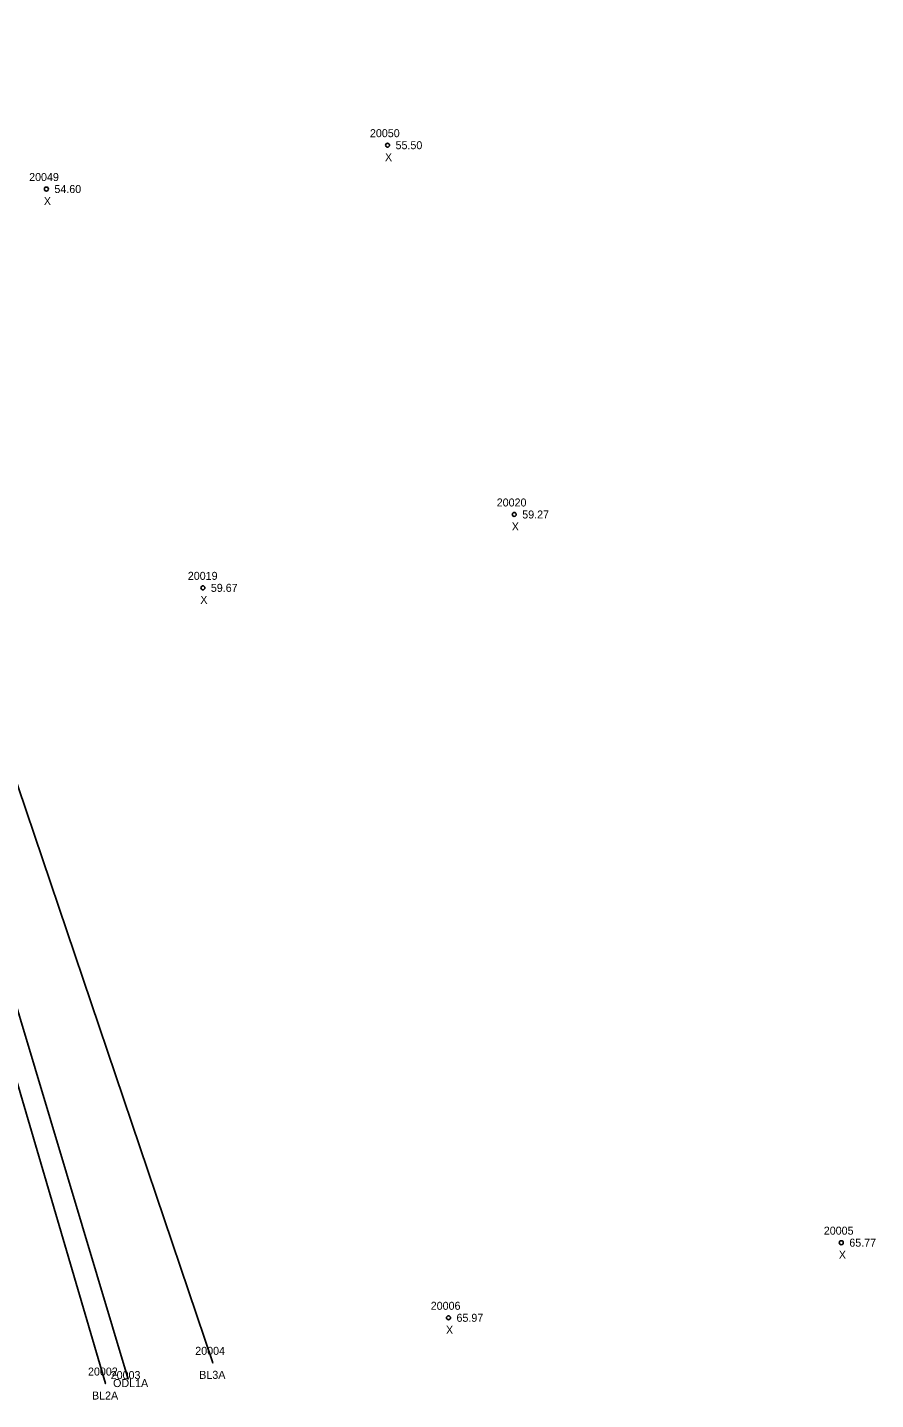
# Model space of a CAD drawing. Extents: x 2445178 to 2446260, y 791158 to 792318.
# Drawn here: x 2445873 to 2445979.1, y 791182.8 to 791354.3 of the extents above; entities that cross this region are included whole.
import ezdxf

# ---------------------------------------------------------------- set-up
doc = ezdxf.new("R2010")
doc.units = 0
for name, color, linetype in [('RD_DTM_BkLn1', 7, 'Continuous'), ('RD_EX_H2O', 7, 'Continuous'), ('RD_EX_H2O_txCode', 7, 'Continuous'), ('RD_Sketch8', 7, 'Continuous'), ('RD_SMD_Locator', 7, 'Continuous'), ('RD_SMD_Misc', 7, 'Continuous')]:
    doc.layers.add(name, color=color, linetype=linetype)

msp = doc.modelspace()

# ---------------------------------------------------------------- linework, layer by layer
at = {"layer": 'RD_DTM_BkLn1'}
for points in [[(2445882.78, 791184.78), (2445856.18, 791275.27), (2445839.04, 791329.43), (2445822.96, 791388.68), (2445805.7, 791444.65), (2445792.52, 791499.62), (2445777.56, 791559.78), (2445760.75, 791635.11), (2445757, 791668.89), (2445761.65, 791682.26), (2445806.3, 791698.85), (2445844.78, 791714.67)], [(2445896.2, 791187.37), (2445865.75, 791277.36), (2445863.45, 791286.42), (2445844.64, 791330.14), (2445831.75, 791389.47), (2445816.24, 791445.72), (2445804.21, 791499.93), (2445790.09, 791561.7), (2445779.57, 791613.54), (2445773.51, 791630.61), (2445764.7, 791668.39), (2445768.27, 791675.25), (2445808.12, 791695.24), (2445844.78, 791714.67)]]:
    msp.add_lwpolyline(points, dxfattribs=at)
at = {"layer": 'RD_EX_H2O'}
msp.add_lwpolyline([(2445885.63, 791185.34), (2445858.54, 791275.66), (2445841.27, 791329.71), (2445824.98, 791389.05), (2445808.2, 791445.07), (2445795.15, 791500.08), (2445780.4, 791559.92), (2445764.43, 791632.51), (2445759.72, 791668.56), (2445764.88, 791679.11), (2445806.8, 791696.09), (2445844.78, 791714.67)], dxfattribs=at)
at = {"layer": 'RD_SMD_Locator'}
for centre, radius in [((2445918.04, 791339.57), 0.25), ((2445875.39, 791334.09), 0.25), ((2445933.88, 791293.41), 0.25), ((2445894.95, 791284.24), 0.25), ((2445974.77, 791202.39), 0.25), ((2445925.66, 791193), 0.25), ((2445896.2, 791187.37), 0.001), ((2445882.78, 791184.78), 0.001), ((2445885.63, 791185.34), 0.001)]:
    msp.add_circle(centre, radius, dxfattribs=at)

# ---------------------------------------------------------------- texts
at = {"layer": 'RD_EX_H2O_txCode'}
for s, p in [('20003', (2445883.43, 791185.34)), ('ODL1A', (2445883.73, 791184.34))]:
    msp.add_text(s, height=1, dxfattribs=at).set_placement(p)
at = {"layer": 'RD_Sketch8'}
for s, p in [('20050', (2445915.84, 791340.57)), ('55.50', (2445919.04, 791339.07)), ('X', (2445917.72, 791337.57)), ('20049', (2445873.23, 791335.09)), ('54.60', (2445876.39, 791333.59)), ('X', (2445875.07, 791332.09)), ('20020', (2445931.69, 791294.41)), ('59.27', (2445934.88, 791292.91)), ('X', (2445933.57, 791291.41)), ('20019', (2445893.07, 791285.24)), ('59.67', (2445895.95, 791283.74)), ('X', (2445894.63, 791282.24)), ('20005', (2445972.58, 791203.39)), ('65.77', (2445975.77, 791201.89)), ('X', (2445974.46, 791200.39)), ('20006', (2445923.44, 791194)), ('65.97', (2445926.66, 791192.5)), ('X', (2445925.35, 791191))]:
    msp.add_text(s, height=1, dxfattribs=at).set_placement(p)
at = {"layer": 'RD_SMD_Misc'}
for s, p in [('20004', (2445894, 791188.37)), ('20002', (2445880.59, 791185.78)), ('BL3A', (2445894.5, 791185.37)), ('BL2A', (2445881.09, 791182.78))]:
    msp.add_text(s, height=1, dxfattribs=at).set_placement(p)

doc.saveas('drawing.dxf')
